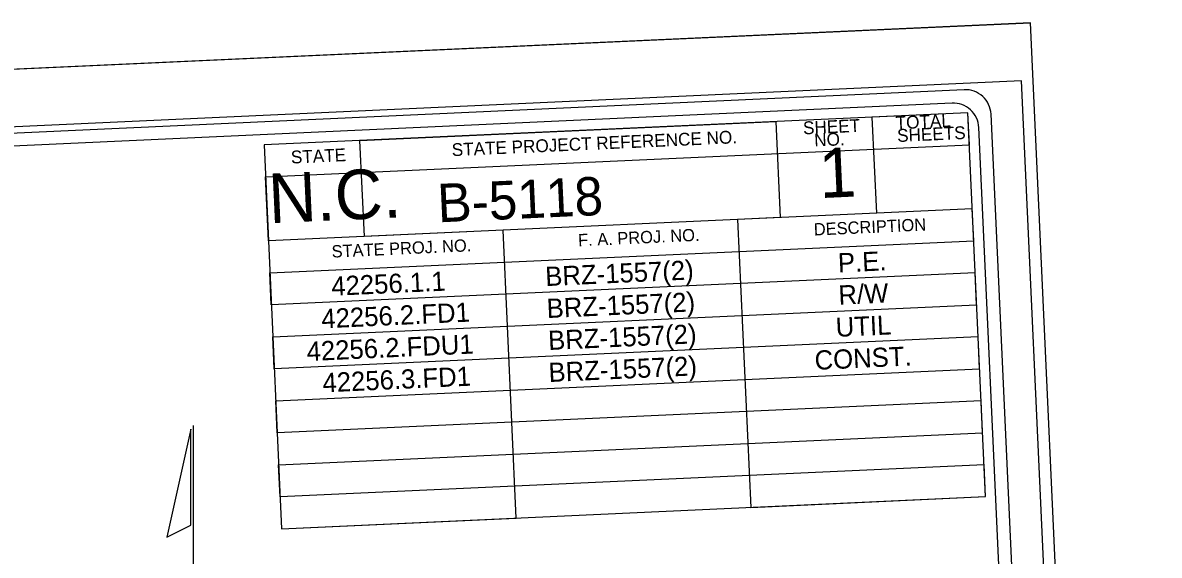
# Model space of a CAD drawing. Extents: x 1190067 to 1192950, y 891516 to 893460.
# Drawn here: x 1192773 to 1192950.4, y 893293.3 to 893376.5 of the extents above; entities that cross this region are included whole.
import ezdxf

# ---------------------------------------------------------------- set-up
doc = ezdxf.new("R2010")
doc.units = 0
for name, color, linetype in [('Sheet Cutting Line CELL', 7, 'Continuous'), ('Sheet Data Field CELL', 7, 'Continuous'), ('Sheet North Arrow CELL', 7, 'Continuous'), ('Sheet Plot Border Inside CELL', 7, 'Continuous'), ('Sheet Plot Border Outside CELL', 7, 'Continuous'), ('Sheet Title CELL', 7, 'Continuous')]:
    doc.layers.add(name, color=color, linetype=linetype)

msp = doc.modelspace()

# ---------------------------------------------------------------- linework, layer by layer
at = {"layer": 'Sheet Cutting Line CELL'}
msp.add_line((1192257.43, 893345.67), (1192930.33, 893376.46), dxfattribs=at)
at = {"layer": 'Sheet North Arrow CELL'}
msp.add_line((1192799.69, 893248.57), (1192799.69, 893313.57), dxfattribs=at)
msp.add_lwpolyline([(1192799.24, 893313), (1192795.53, 893296.12), (1192799.24, 893298)], close=True, dxfattribs=at)
at = {"layer": 'Sheet Plot Border Inside CELL'}
msp.add_lwpolyline([(1192282.33, 892915.34), (1192948.23, 892945.8), (1192928.94, 893367.4), (1192263.04, 893336.94)], close=True, dxfattribs=at)
at = {"layer": 'Sheet Plot Border Outside CELL'}
msp.add_lwpolyline([(1192930.33, 893376.46), (1192257.43, 893345.67), (1192277.54, 892906.14), (1192950.44, 892936.92)], close=True, dxfattribs=at)
at = {"layer": 'Sheet Title CELL'}
for points in [[(1192920, 893365.97), (1192328.61, 893338.92)], [(1192918.09, 893363.88), (1192350.69, 893337.92)], [(1192813.42, 893297.44), (1192923.31, 893302.46), (1192923.08, 893307.45), (1192813.19, 893302.43), (1192812.96, 893307.42), (1192922.85, 893312.45), (1192922.62, 893317.44), (1192812.74, 893312.41), (1192812.51, 893317.41), (1192922.39, 893322.44), (1192922.16, 893327.44), (1192812.28, 893322.41), (1192812.05, 893327.4), (1192921.93, 893332.43), (1192921.71, 893337.42), (1192811.82, 893332.39), (1192811.59, 893337.39), (1192921.48, 893342.42), (1192921.25, 893347.42), (1192811.36, 893342.39), (1192810.91, 893352.38), (1192920.79, 893357.41), (1192920.56, 893362.4), (1192810.68, 893357.37), (1192813.42, 893297.44), (1192850.04, 893299.11), (1192847.99, 893344.06), (1192826.35, 893343.07), (1192825.66, 893358.06), (1192890.6, 893361.02), (1192891.28, 893346.04), (1192884.61, 893345.74), (1192886.66, 893300.79), (1192923.31, 893302.46), (1192920.56, 893362.4), (1192905.58, 893361.71), (1192906.27, 893346.73)], [(1192943.01, 892950.6), (1192924.18, 893362.16)], [(1192937.54, 893026.42), (1192922.27, 893360.08)]]:
    msp.add_lwpolyline(points, dxfattribs=at)
for centre in [(1192920.18, 893362), (1192918.28, 893359.91)]:
    msp.add_arc(centre, 4, 2.6195, 92.6195, dxfattribs=at)

# ---------------------------------------------------------------- texts
at = {"layer": 'Sheet Data Field CELL'}
for s, height, p in [('B-5118    ', 6, (1192837.87, 893345.28)), ('P.E.', 3, (1192900.34, 893337.46)), ('BRZ-1557(2)   ', 3, (1192854.65, 893335.33)), ('42256.1.1 ', 3, (1192821.25, 893333.81)), ('R/W', 3, (1192900.42, 893332.43)), ('BRZ-1557(2)   ', 3, (1192854.87, 893330.34)), ('42256.2.FD1', 3, (1192819.7, 893328.73)), ('UTIL', 3, (1192899.99, 893327.4)), ('BRZ-1557(2)   ', 3, (1192855.1, 893325.35)), ('42256.2.FDU1 ', 3, (1192817.4, 893323.62)), ('CONST.', 3, (1192896.7, 893322.25)), ('BRZ-1557(2)   ', 3, (1192855.16, 893320.35)), ('42256.3.FD1', 3, (1192819.87, 893318.73))]:
    msp.add_text(s, height=height, rotation=2.6195, dxfattribs=at).set_placement(p)
at = {"layer": 'Sheet Title CELL'}
for s, height, p in [('TOTAL', 2, (1192909.33, 893359.82)), ('SHEET', 2, (1192894.87, 893359.02)), ('SHEETS', 2, (1192909.56, 893357.83)), ('STATE PROJECT REFERENCE NO.', 1.9999, (1192840.03, 893355.61)), ('NO.', 2, (1192896.62, 893357.12)), ('STATE', 2, (1192814.92, 893354.46)), ('1', 7.74, (1192897.49, 893349.07)), ('N.C.', 7.74, (1192811.54, 893345.14)), ('DESCRIPTION', 1.92, (1192896.55, 893343.22)), ('F. A. PROJ. NO.', 1.92, (1192859.75, 893341.54)), ('STATE PROJ. NO.', 1.92, (1192821.27, 893339.78))]:
    msp.add_text(s, height=height, rotation=2.6195, dxfattribs=at).set_placement(p)

doc.saveas('drawing.dxf')
